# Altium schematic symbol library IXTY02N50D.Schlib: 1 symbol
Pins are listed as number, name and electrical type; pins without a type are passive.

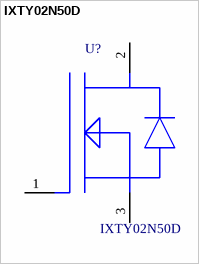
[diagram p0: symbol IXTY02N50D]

## IXTY02N50D
designator U?
DISCRETE, MOSFET N-CH 500V 200MA, DPAK; Manufacturer: IXYS; SymbolCreator: x0199378
pins: 1 G, 2 D, 3 S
